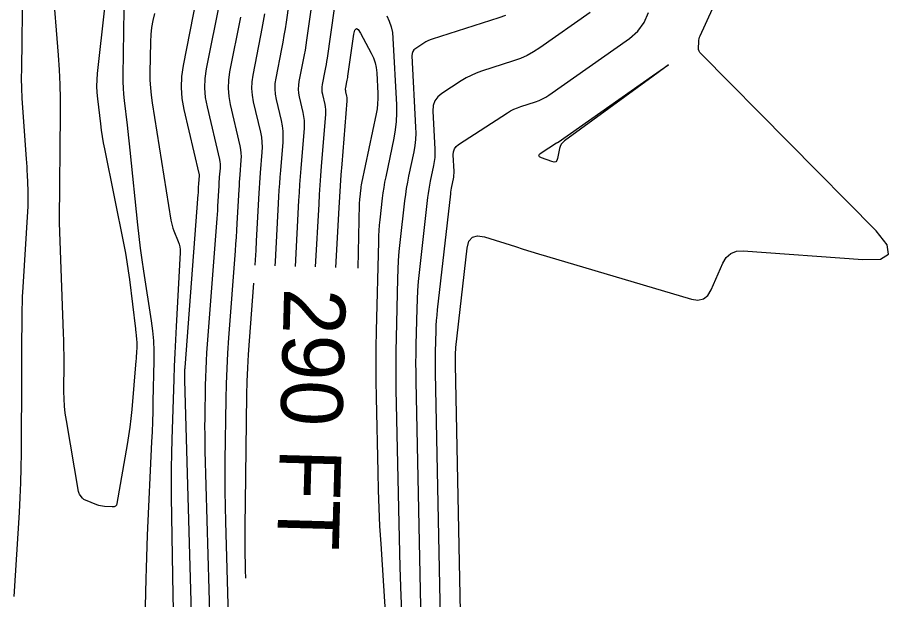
# Model space of a CAD drawing. Extents: x 1768942 to 1774819, y 723037 to 732099.
# Drawn here: x 1770861.8 to 1770946.5, y 724705.9 to 724762.5 of the extents above; entities that cross this region are included whole.
import ezdxf

# ---------------------------------------------------------------- set-up
doc = ezdxf.new("R2010")
doc.units = 0
doc.layers.add('R_Contour Annot', color=7, linetype='Continuous')
doc.layers.add('R_Contours', color=7, linetype='Continuous')

msp = doc.modelspace()

# ---------------------------------------------------------------- linework, layer by layer
at = {"layer": 'R_Contours'}
for points in [[(1770905.325, 724680.713), (1770904.355, 724728.766), (1770904.353, 724728.907), (1770904.353, 724729.048), (1770904.354, 724729.188), (1770904.356, 724729.329), (1770904.369, 724729.891), (1770904.374, 724730.032), (1770904.382, 724730.172), (1770904.393, 724730.312), (1770904.407, 724730.452), (1770905.5, 724740.114), (1770905.671, 724740.77), (1770906.008, 724741.17), (1770906.511, 724741.314), (1770907.18, 724741.203), (1770910.185, 724740.248), (1770910.937, 724740.012), (1770911.69, 724739.778), (1770912.444, 724739.549), (1770913.199, 724739.323), (1770927.296, 724735.144), (1770927.925, 724735.049), (1770928.455, 724735.167), (1770928.885, 724735.498), (1770929.216, 724736.042), (1770930.34, 724738.644), (1770930.674, 724739.207), (1770931.114, 724739.594), (1770931.662, 724739.806), (1770932.315, 724739.842), (1770943.961, 724738.992), (1770945.673, 724739.047), (1770946.458, 724739.53), (1770946.316, 724740.441), (1770945.246, 724741.779), (1770928.196, 724759.029), (1770928.101, 724759.144), (1770928.035, 724759.271), (1770927.996, 724759.408), (1770927.986, 724759.557), (1770928, 724760.173), (1770928.011, 724760.325), (1770928.037, 724760.474), (1770928.078, 724760.619), (1770928.134, 724760.761), (1770934.485, 724774.698)], [(1770888.797, 724738.331), (1770889.149, 724744.742), (1770889.194, 724745.523), (1770889.245, 724746.303), (1770889.3, 724747.083), (1770889.361, 724747.862), (1770889.675, 724751.765), (1770889.691, 724752.15), (1770889.678, 724752.534), (1770889.634, 724752.915), (1770889.56, 724753.294), (1770889.206, 724754.805), (1770889.138, 724755.184), (1770889.111, 724755.563), (1770889.124, 724755.942), (1770889.179, 724756.323), (1770889.592, 724758.415), (1770889.683, 724758.891), (1770889.767, 724759.369), (1770889.845, 724759.847), (1770889.917, 724760.326), (1770890.992, 724767.847)], [(1770890.764, 724738.278), (1770891.1, 724744.386), (1770891.153, 724745.308), (1770891.213, 724746.23), (1770891.278, 724747.152), (1770891.35, 724748.073), (1770891.755, 724753.104), (1770891.766, 724753.351), (1770891.757, 724753.596), (1770891.729, 724753.839), (1770891.682, 724754.082), (1770891.456, 724755.047), (1770891.412, 724755.289), (1770891.395, 724755.531), (1770891.403, 724755.774), (1770891.438, 724756.017), (1770891.702, 724757.354), (1770891.76, 724757.659), (1770891.814, 724757.964), (1770891.864, 724758.269), (1770891.91, 724758.576), (1770893.295, 724768.263)], [(1770886.829, 724738.384), (1770886.852, 724738.798), (1770887.198, 724745.099), (1770887.236, 724745.737), (1770887.277, 724746.376), (1770887.322, 724747.014), (1770887.371, 724747.652), (1770887.595, 724750.425), (1770887.617, 724750.95), (1770887.598, 724751.472), (1770887.539, 724751.991), (1770887.439, 724752.506), (1770886.957, 724754.563), (1770886.864, 724755.078), (1770886.827, 724755.594), (1770886.846, 724756.111), (1770886.92, 724756.628), (1770887.482, 724759.476), (1770887.605, 724760.124), (1770887.72, 724760.774), (1770887.826, 724761.425), (1770887.924, 724762.077), (1770888.69, 724767.431)], [(1770879.522, 724766.162), (1770877.883, 724757.851), (1770877.73, 724756.784), (1770877.691, 724755.719), (1770877.767, 724754.656), (1770877.959, 724753.595), (1770879.417, 724747.376), (1770879.43, 724747.306), (1770879.438, 724747.236), (1770879.441, 724747.165), (1770879.438, 724747.094), (1770879.415, 724746.809), (1770879.409, 724746.738), (1770879.404, 724746.667), (1770879.4, 724746.595), (1770879.396, 724746.524), (1770879.359, 724745.859), (1770879.351, 724745.725), (1770879.343, 724745.59), (1770879.334, 724745.456), (1770879.324, 724745.321), (1770878.048, 724728.494), (1770878.041, 724728.392), (1770878.035, 724728.29), (1770878.032, 724728.187), (1770878.029, 724728.085), (1770878.024, 724727.674), (1770878.023, 724727.572), (1770878.023, 724727.469), (1770878.024, 724727.367), (1770878.027, 724727.264), (1770879.419, 724678.526)], [(1770861.458, 724706.235), (1770861.976, 724714.402), (1770862.057, 724715.844), (1770862.117, 724717.287), (1770862.156, 724718.731), (1770862.173, 724720.175), (1770862.21, 724728.038), (1770862.211, 724728.441), (1770862.213, 724728.844), (1770862.214, 724729.247), (1770862.216, 724729.65), (1770862.221, 724731.32), (1770862.222, 724731.693), (1770862.225, 724732.067), (1770862.228, 724732.44), (1770862.232, 724732.813), (1770862.251, 724734.307), (1770862.258, 724734.68), (1770862.269, 724735.053), (1770862.285, 724735.426), (1770862.305, 724735.799), (1770862.81, 724744.188), (1770862.828, 724744.57), (1770862.836, 724744.952), (1770862.834, 724745.335), (1770862.821, 724745.717), (1770862.751, 724747.247), (1770862.732, 724747.63), (1770862.711, 724748.012), (1770862.687, 724748.394), (1770862.661, 724748.776), (1770862.304, 724753.739), (1770862.245, 724754.694), (1770862.208, 724755.649), (1770862.191, 724756.605), (1770862.195, 724757.561), (1770862.32, 724765.726)], [(1770870.236, 724763.479), (1770869.534, 724757.091), (1770869.484, 724756.477), (1770869.469, 724755.864), (1770869.491, 724755.251), (1770869.547, 724754.638), (1770869.845, 724752.186), (1770869.925, 724751.574), (1770870.018, 724750.964), (1770870.122, 724750.356), (1770870.238, 724749.75), (1770872.116, 724740.438), (1770872.277, 724739.599), (1770872.421, 724738.757), (1770872.549, 724737.912), (1770872.66, 724737.065), (1770873.245, 724732.25), (1770873.262, 724732.112), (1770873.277, 724731.974), (1770873.292, 724731.837), (1770873.307, 724731.699), (1770873.363, 724731.148), (1770873.374, 724731.01), (1770873.38, 724730.872), (1770873.381, 724730.734), (1770873.377, 724730.596), (1770873.341, 724729.839), (1770873.332, 724729.667), (1770873.322, 724729.494), (1770873.309, 724729.322), (1770873.296, 724729.151), (1770872.888, 724724.397), (1770872.806, 724723.549), (1770872.706, 724722.703), (1770872.587, 724721.859), (1770872.449, 724721.018), (1770871.446, 724715.279), (1770871.394, 724715.117), (1770871.302, 724715.005), (1770871.171, 724714.943), (1770871.001, 724714.931), (1770870.243, 724714.984), (1770870.055, 724715.004), (1770869.87, 724715.038), (1770869.688, 724715.086), (1770869.509, 724715.148), (1770868.39, 724715.579), (1770868.305, 724715.618), (1770868.228, 724715.667), (1770868.159, 724715.726), (1770868.097, 724715.795), (1770867.863, 724716.093), (1770867.81, 724716.169), (1770867.768, 724716.251), (1770867.736, 724716.337), (1770867.715, 724716.428), (1770866.539, 724723.346), (1770866.435, 724724.046), (1770866.361, 724724.749), (1770866.318, 724725.454), (1770866.305, 724726.162), (1770866.313, 724728.997), (1770866.312, 724729.706), (1770866.303, 724730.414), (1770866.288, 724731.123), (1770866.265, 724731.831), (1770865.869, 724742.568), (1770865.869, 724742.579), (1770865.869, 724742.59), (1770865.869, 724742.601), (1770865.87, 724742.612), (1770865.873, 724742.655), (1770865.873, 724742.666), (1770865.874, 724742.677), (1770865.874, 724742.688), (1770865.874, 724742.699), (1770865.871, 724742.766), (1770865.871, 724742.781), (1770865.871, 724742.796), (1770865.871, 724742.811), (1770865.871, 724742.826), (1770865.974, 724753.205), (1770865.972, 724754.62), (1770865.938, 724756.034), (1770865.873, 724757.447), (1770865.776, 724758.859), (1770865.221, 724765.774)], [(1770881.488, 724764.367), (1770880.142, 724757.545), (1770880.009, 724756.616), (1770879.975, 724755.688), (1770880.042, 724754.762), (1770880.208, 724753.837), (1770881.41, 724748.713), (1770881.45, 724748.504), (1770881.474, 724748.294), (1770881.482, 724748.083), (1770881.473, 724747.871), (1770881.404, 724747.02), (1770881.388, 724746.807), (1770881.372, 724746.594), (1770881.359, 724746.381), (1770881.346, 724746.168), (1770881.237, 724744.182), (1770881.214, 724743.78), (1770881.189, 724743.378), (1770881.162, 724742.976), (1770881.132, 724742.575), (1770880.174, 724729.937), (1770880.12, 724729.141), (1770880.078, 724728.346), (1770880.048, 724727.549), (1770880.031, 724726.752), (1770879.987, 724723.563), (1770879.98, 724722.766), (1770879.982, 724721.969), (1770879.992, 724721.172), (1770880.01, 724720.375), (1770881.165, 724679.936)], [(1770874.176, 724702.536), (1770874.289, 724707.925), (1770874.315, 724708.99), (1770874.348, 724710.055), (1770874.387, 724711.119), (1770874.433, 724712.183), (1770874.853, 724721.256), (1770874.895, 724722.24), (1770874.932, 724723.224), (1770874.963, 724724.208), (1770874.989, 724725.193), (1770875.079, 724729.131), (1770875.08, 724730.114), (1770875.037, 724731.094), (1770874.95, 724732.071), (1770874.82, 724733.045), (1770874.069, 724737.853), (1770873.901, 724738.98), (1770873.748, 724740.108), (1770873.61, 724741.239), (1770873.488, 724742.371), (1770872.751, 724749.641), (1770872.688, 724750.245), (1770872.623, 724750.848), (1770872.554, 724751.451), (1770872.482, 724752.054), (1770872.189, 724754.465), (1770872.126, 724755.068), (1770872.084, 724755.673), (1770872.063, 724756.278), (1770872.063, 724756.885), (1770872.168, 724763.311)], [(1770875.11, 724762.931), (1770874.938, 724762.252), (1770874.811, 724761.566), (1770874.732, 724760.872), (1770874.699, 724760.172), (1770874.657, 724757.169), (1770874.662, 724756.435), (1770874.699, 724755.704), (1770874.768, 724754.974), (1770874.868, 724754.247), (1770876.689, 724742.84), (1770876.74, 724742.568), (1770876.807, 724742.302), (1770876.889, 724742.039), (1770876.987, 724741.781), (1770877.409, 724740.757), (1770877.5, 724740.498), (1770877.56, 724740.235), (1770877.59, 724739.966), (1770877.591, 724739.692), (1770877.2, 724732.49), (1770877.134, 724731.197), (1770877.074, 724729.904), (1770877.021, 724728.611), (1770876.974, 724727.317), (1770876.782, 724721.515), (1770876.744, 724720.116), (1770876.723, 724718.718), (1770876.719, 724717.319), (1770876.732, 724715.92), (1770876.882, 724706.351), (1770876.905, 724704.963)], [(1770885.791, 724762.88), (1770885.676, 724762.178), (1770885.552, 724761.478), (1770885.419, 724760.779), (1770884.661, 724756.934), (1770884.567, 724756.279), (1770884.543, 724755.625), (1770884.59, 724754.973), (1770884.707, 724754.321), (1770885.395, 724751.387), (1770885.49, 724750.901), (1770885.546, 724750.412), (1770885.563, 724749.92), (1770885.542, 724749.425), (1770885.382, 724747.441), (1770885.344, 724746.945), (1770885.309, 724746.448), (1770885.277, 724745.952), (1770885.248, 724745.455), (1770884.994, 724740.826), (1770884.94, 724739.89), (1770884.881, 724738.953), (1770884.846, 724738.438)], [(1770917.441, 724763.025), (1770912.553, 724759.585), (1770911.947, 724759.193), (1770911.318, 724758.849), (1770910.664, 724758.553), (1770909.986, 724758.307), (1770906.904, 724757.317), (1770906.381, 724757.13), (1770905.875, 724756.91), (1770905.384, 724756.657), (1770904.908, 724756.37), (1770903.039, 724755.158), (1770902.634, 724754.823), (1770902.352, 724754.425), (1770902.195, 724753.963), (1770902.162, 724753.439), (1770902.354, 724749.723), (1770902.362, 724749.328), (1770902.344, 724748.935), (1770902.301, 724748.544), (1770902.232, 724748.155), (1770901.906, 724746.603), (1770901.829, 724746.214), (1770901.761, 724745.824), (1770901.703, 724745.432), (1770901.654, 724745.039), (1770900.829, 724737.747), (1770900.74, 724736.869), (1770900.67, 724735.99), (1770900.621, 724735.109), (1770900.59, 724734.228), (1770900.509, 724730.697), (1770900.493, 724729.815), (1770900.487, 724728.932), (1770900.491, 724728.05), (1770900.504, 724727.167), (1770901.009, 724702.151)], [(1770903.167, 724691.432), (1770902.43, 724727.967), (1770902.422, 724728.478), (1770902.42, 724728.99), (1770902.424, 724729.502), (1770902.433, 724730.013), (1770902.48, 724732.059), (1770902.497, 724732.571), (1770902.526, 724733.081), (1770902.567, 724733.591), (1770902.618, 724734.099), (1770903.893, 724745.373), (1770903.916, 724745.557), (1770903.943, 724745.74), (1770903.975, 724745.923), (1770904.011, 724746.105), (1770904.164, 724746.832), (1770904.196, 724747.014), (1770904.216, 724747.197), (1770904.224, 724747.381), (1770904.221, 724747.566), (1770904.138, 724749.168), (1770904.158, 724749.479), (1770904.251, 724749.751), (1770904.417, 724749.987), (1770904.657, 724750.185), (1770909.401, 724753.262), (1770909.716, 724753.452), (1770910.042, 724753.62), (1770910.379, 724753.766), (1770910.725, 724753.891), (1770912.133, 724754.343), (1770912.479, 724754.468), (1770912.812, 724754.619), (1770913.133, 724754.794), (1770913.442, 724754.994), (1770921.268, 724760.5), (1770922.097, 724761.219), (1770922.714, 724762.059), (1770923.117, 724763.019)], [(1770883.453, 724762.573), (1770882.401, 724757.24), (1770882.288, 724756.447), (1770882.259, 724755.656), (1770882.316, 724754.867), (1770882.458, 724754.079), (1770883.402, 724750.05), (1770883.47, 724749.702), (1770883.51, 724749.353), (1770883.522, 724749.002), (1770883.507, 724748.648), (1770883.393, 724747.23), (1770883.366, 724746.876), (1770883.341, 724746.521), (1770883.318, 724746.166), (1770883.297, 724745.811), (1770883.115, 724742.504), (1770883.077, 724741.835), (1770883.035, 724741.165), (1770882.989, 724740.496), (1770882.94, 724739.828), (1770882.3, 724731.379), (1770882.198, 724729.891), (1770882.12, 724728.401), (1770882.065, 724726.911), (1770882.033, 724725.42), (1770881.95, 724719.452), (1770881.937, 724717.96), (1770881.94, 724716.469), (1770881.959, 724714.977), (1770881.994, 724713.486), (1770882.912, 724681.346)], [(1770897.689, 724762.684), (1770897.927, 724762.167), (1770898.106, 724761.634), (1770898.226, 724761.084), (1770898.285, 724760.518), (1770898.621, 724754.037), (1770898.637, 724753.222), (1770898.6, 724752.411), (1770898.511, 724751.604), (1770898.369, 724750.801), (1770897.576, 724747.027), (1770897.474, 724746.511), (1770897.384, 724745.993), (1770897.306, 724745.473), (1770897.241, 724744.951), (1770897.005, 724742.859), (1770896.951, 724742.336), (1770896.91, 724741.812), (1770896.88, 724741.287), (1770896.862, 724740.761), (1770896.662, 724732.066), (1770896.633, 724730.442), (1770896.622, 724728.817), (1770896.629, 724727.192), (1770896.653, 724725.568), (1770896.799, 724718.321), (1770896.844, 724716.572), (1770896.907, 724714.824), (1770896.99, 724713.077), (1770897.091, 724711.33), (1770898.68, 724686.336)], [(1770909.222, 724762.744), (1770908.573, 724762.508), (1770902.107, 724760.431), (1770901.889, 724760.353), (1770901.678, 724760.261), (1770901.473, 724760.155), (1770901.275, 724760.035), (1770900.495, 724759.53), (1770900.326, 724759.39), (1770900.208, 724759.224), (1770900.143, 724759.031), (1770900.129, 724758.812), (1770900.487, 724751.88), (1770900.499, 724751.275), (1770900.472, 724750.673), (1770900.406, 724750.074), (1770900.3, 724749.478), (1770899.801, 724747.101), (1770899.683, 724746.505), (1770899.58, 724745.908), (1770899.49, 724745.308), (1770899.415, 724744.705), (1770898.957, 724740.655), (1770898.868, 724739.778), (1770898.798, 724738.9), (1770898.748, 724738.021), (1770898.718, 724737.14), (1770898.585, 724731.382), (1770898.563, 724730.128), (1770898.555, 724728.875), (1770898.56, 724727.621), (1770898.578, 724726.367), (1770898.87, 724711.912), (1770898.942, 724709.085), (1770899.045, 724706.26), (1770899.179, 724703.436)], [(1770892.732, 724738.225), (1770893.051, 724744.029), (1770893.112, 724745.094), (1770893.181, 724746.157), (1770893.257, 724747.221), (1770893.339, 724748.283), (1770893.836, 724754.444), (1770893.84, 724754.551), (1770893.836, 724754.658), (1770893.824, 724754.764), (1770893.804, 724754.869), (1770893.705, 724755.29), (1770893.686, 724755.395), (1770893.679, 724755.5), (1770893.682, 724755.606), (1770893.698, 724755.712), (1770893.812, 724756.294), (1770893.838, 724756.426), (1770893.861, 724756.559), (1770893.883, 724756.692), (1770893.903, 724756.825), (1770894.487, 724760.912), (1770894.585, 724761.318), (1770894.727, 724761.473), (1770894.913, 724761.375), (1770895.143, 724761.026), (1770896.18, 724759.063), (1770896.39, 724758.609), (1770896.547, 724758.141), (1770896.652, 724757.659), (1770896.704, 724757.162), (1770896.808, 724755.146), (1770896.818, 724754.644), (1770896.795, 724754.143), (1770896.74, 724753.646), (1770896.653, 724753.151), (1770895.238, 724746.417), (1770895.205, 724746.249), (1770895.176, 724746.081), (1770895.151, 724745.912), (1770895.129, 724745.743), (1770895.052, 724745.063), (1770895.035, 724744.893), (1770895.022, 724744.723), (1770895.012, 724744.552), (1770895.006, 724744.381), (1770894.863, 724738.167)], [(1770884.719, 724736.696), (1770884.294, 724731.083), (1770884.205, 724729.771), (1770884.136, 724728.459), (1770884.087, 724727.145), (1770884.058, 724725.83), (1770883.913, 724715.341), (1770883.895, 724713.155), (1770883.899, 724710.968), (1770883.927, 724708.782), (1770883.945, 724708.002)]]:
    msp.add_lwpolyline(points, dxfattribs=at)
msp.add_lwpolyline([(1770914.294, 724750.383), (1770914.307, 724750.389), (1770914.319, 724750.396), (1770914.331, 724750.404), (1770923.527, 724756.872), (1770924.667, 724757.67), (1770925.054, 724757.927), (1770924.686, 724757.643), (1770923.564, 724756.819), (1770914.962, 724750.54), (1770914.785, 724750.386), (1770914.645, 724750.207), (1770914.542, 724750.005), (1770914.475, 724749.779), (1770914.285, 724748.829), (1770914.215, 724748.631), (1770914.1, 724748.514), (1770913.94, 724748.478), (1770913.736, 724748.522), (1770912.726, 724748.898), (1770912.54, 724748.995), (1770912.469, 724749.105), (1770912.514, 724749.228), (1770912.675, 724749.363), (1770914.176, 724750.337), (1770914.188, 724750.344), (1770914.201, 724750.351), (1770914.214, 724750.356), (1770914.227, 724750.361), (1770914.281, 724750.378)], close=True, dxfattribs=at)

# ---------------------------------------------------------------- texts
at = {"layer": 'R_Contour Annot'}
msp.add_text('290 FT', height=6, rotation=268.45372, dxfattribs=at).set_placement((1770887.709, 724736.257))

doc.saveas('drawing.dxf')
